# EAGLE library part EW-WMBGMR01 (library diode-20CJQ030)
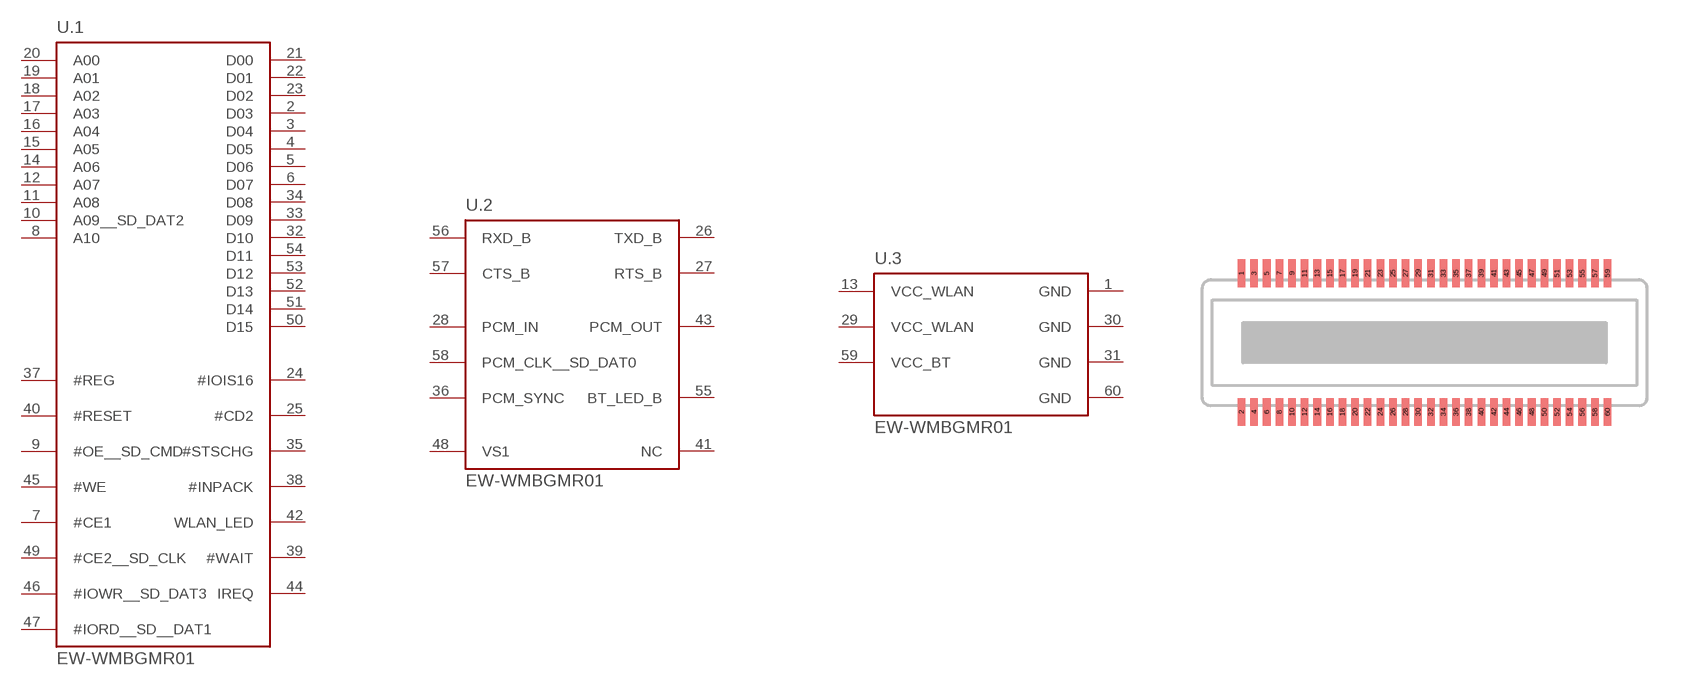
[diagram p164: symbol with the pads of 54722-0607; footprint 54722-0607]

Designator prefix U; gates .1=EW-WMBGMR01-CF .2=EW-WMBGMR01-BT .3=EW-WMBGMR01-PWR

## EW-WMBGMR01  [54722-0607]
1  .3:GND  pwr
2  .1:D03
3  .1:D04
4  .1:D05
5  .1:D06
6  .1:D07
7  .1:#CE1  in
8  .1:A10  in
9  .1:#OE__SD_CMD  in
10  .1:A09__SD_DAT2  in
11  .1:A08  in
12  .1:A07  in
13  .3:VCC_WLAN  pwr
14  .1:A06  in
15  .1:A05  in
16  .1:A04  in
17  .1:A03  in
18  .1:A02  in
19  .1:A01  in
20  .1:A00  in
21  .1:D00
22  .1:D01
23  .1:D02
24  .1:#IOIS16  out
25  .1:#CD2  out
26  .2:TXD_B  out
27  .2:RTS_B  out
28  .2:PCM_IN  in
29  .3:VCC_WLAN  pwr
30  .3:GND  pwr
31  .3:GND  pwr
32  .1:D10
33  .1:D09
34  .1:D08
35  .1:#STSCHG  out
36  .2:PCM_SYNC  out
37  .1:#REG  in
38  .1:#INPACK  out
39  .1:#WAIT  out
40  .1:#RESET  in
41  .2:NC  nc
42  .1:WLAN_LED  out
43  .2:PCM_OUT  out
44  .1:IREQ  out
45  .1:#WE  in
46  .1:#IOWR__SD_DAT3  in
47  .1:#IORD__SD__DAT1  in
48  .2:VS1  pas
49  .1:#CE2__SD_CLK  in
50  .1:D15
51  .1:D14
52  .1:D13
53  .1:D12
54  .1:D11
55  .2:BT_LED_B  out
56  .2:RXD_B  in
57  .2:CTS_B  in
58  .2:PCM_CLK__SD_DAT0  in
59  .3:VCC_BT  pwr
60  .3:GND  pwr

## Footprint 54722-0607 (pad centres in mm)
Molex 54722-0607 Bord to Board connector 60pin.
smd 0.3 x 1.1: 1 -7.25,2.75; 2 -7.25,-2.75; 3 -6.75,2.75; 4 -6.75,-2.75; 5 -6.25,2.75; 6 -6.25,-2.75; 7 -5.75,2.75; 8 -5.75,-2.75; 9 -5.25,2.75; 10 -5.25,-2.75; 11 -4.75,2.75; 12 -4.75,-2.75; 13 -4.25,2.75; 14 -4.25,-2.75; 15 -3.75,2.75; 16 -3.75,-2.75; 17 -3.25,2.75; 18 -3.25,-2.75; 19 -2.75,2.75; 20 -2.75,-2.75; 21 -2.25,2.75; 22 -2.25,-2.75; 23 -1.75,2.75; 24 -1.75,-2.75; 25 -1.25,2.75; 26 -1.25,-2.75; 27 -0.75,2.75; 28 -0.75,-2.75; 29 -0.25,2.75; 30 -0.25,-2.75; 31 0.25,2.75; 32 0.25,-2.75; 33 0.75,2.75; 34 0.75,-2.75; 35 1.25,2.75; 36 1.25,-2.75; 37 1.75,2.75; 38 1.75,-2.75; 39 2.25,2.75; 40 2.25,-2.75; 41 2.75,2.75; 42 2.75,-2.75; 43 3.25,2.75; 44 3.25,-2.75; 45 3.75,2.75; 46 3.75,-2.75; 47 4.25,2.75; 48 4.25,-2.75; 49 4.75,2.75; 50 4.75,-2.75; 51 5.25,2.75; 52 5.25,-2.75; 53 5.75,2.75; 54 5.75,-2.75; 55 6.25,2.75; 56 6.25,-2.75; 57 6.75,2.75; 58 6.75,-2.75; 59 7.25,2.75; 60 7.25,-2.75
